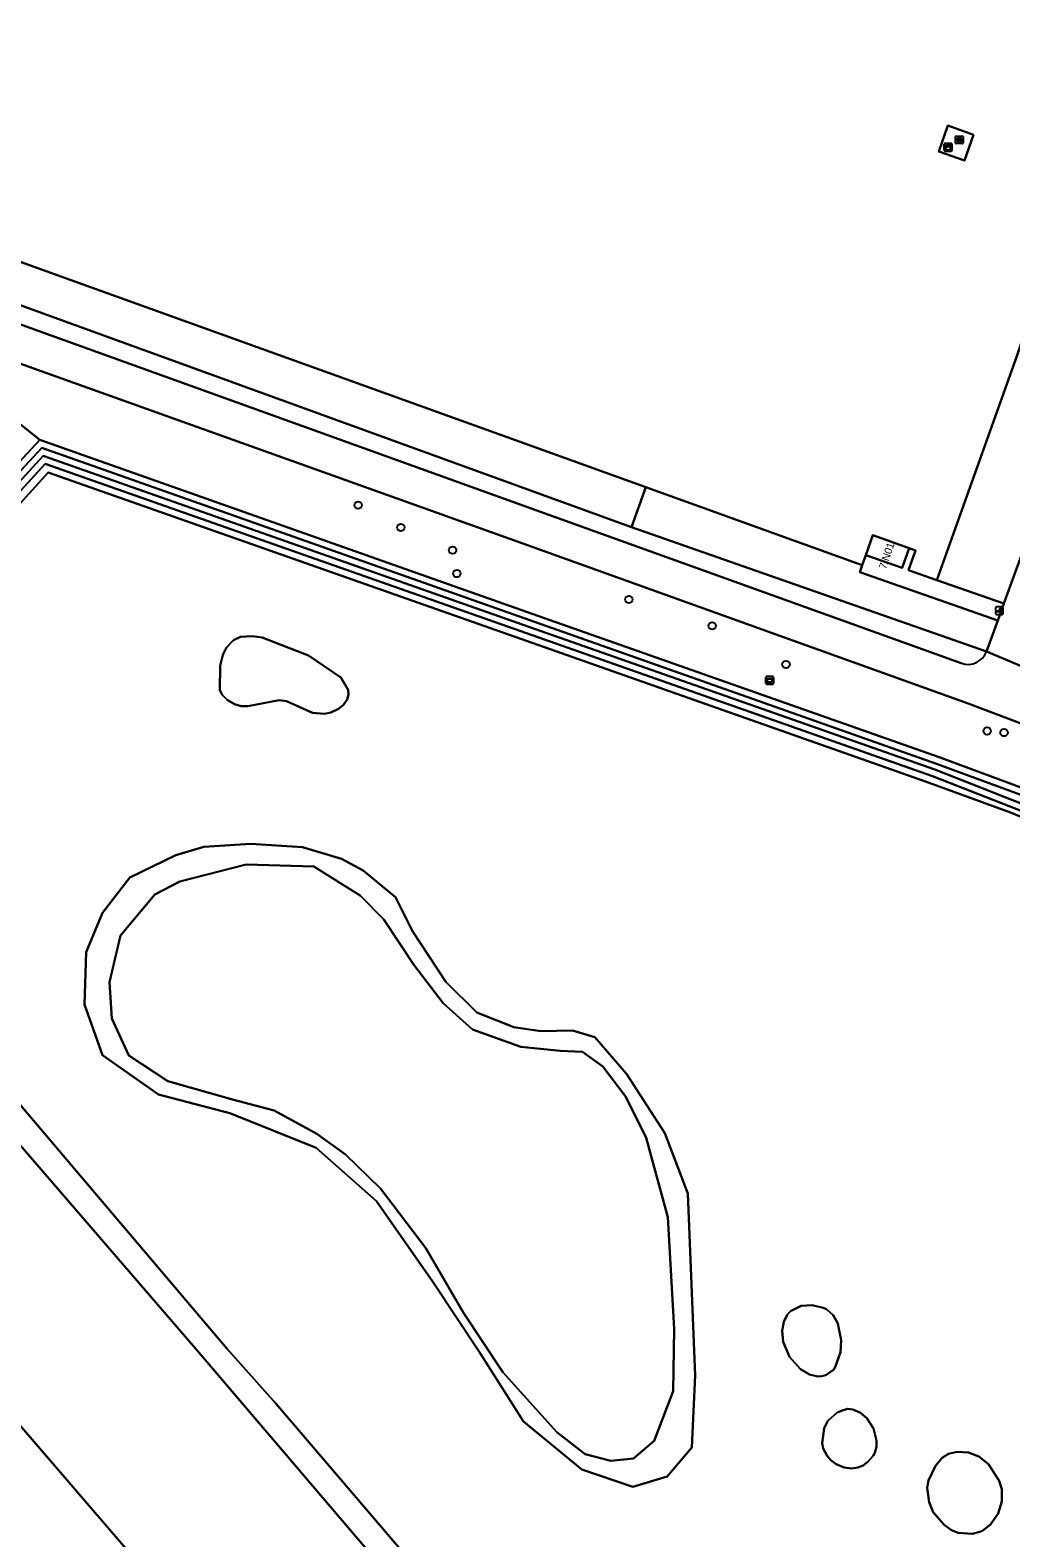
# Model space of a CAD drawing. Extents: x 156061 to 157804, y 383437 to 385640.
# Drawn here: x 156433.8 to 156563.1, y 384975 to 385173.9 of the extents above; entities that cross this region are included whole.
import ezdxf

# ---------------------------------------------------------------- set-up
doc = ezdxf.new("R2010")
doc.units = 0
for name, color, linetype in [('IMGEO_Boom', 7, 'Continuous'), ('IMGEO_Gemengd_bos', 7, 'Continuous'), ('IMGEO_Grasland_overig', 7, 'Continuous'), ('IMGEO_Groenvoorziening', 7, 'Continuous'), ('IMGEO_Kast', 7, 'Continuous'), ('IMGEO_Meer_plas_ven_vijver', 7, 'Continuous'), ('IMGEO_Oever', 7, 'Continuous'), ('IMGEO_Pand', 7, 'Continuous'), ('IMGEO_Pand_nummerreeks', 7, 'Continuous'), ('IMGEO_Poller', 7, 'Continuous'), ('IMGEO_Rijbaan_lokaal_gesloten', 7, 'Continuous'), ('IMGEO_Rioolput', 7, 'Continuous'), ('IMGEO_Terreindeel_open', 7, 'Continuous'), ('IMGEO_Terreindeel_zand', 7, 'Continuous'), ('IMGEO_Verklikker', 7, 'Continuous'), ('IMGEO_Voetpad_open', 7, 'Continuous'), ('IMGEO_Waterloop', 7, 'Continuous')]:
    doc.layers.add(name, color=color, linetype=linetype)

msp = doc.modelspace()

# ---------------------------------------------------------------- linework, layer by layer
at = {"layer": 'IMGEO_Boom'}
for centre in [(156477.05, 385111.22), (156482.67, 385108.28), (156489.5, 385105.3), (156490.07, 385102.2), (156512.75, 385098.79), (156523.74, 385095.32), (156533.49, 385090.22), (156560.03, 385081.44), (156562.25, 385081.23)]:
    msp.add_circle(centre, 0.489, dxfattribs=at)
at = {"layer": 'IMGEO_Gemengd_bos'}
msp.add_lwpolyline([(156581.52, 384855.31), (156560.26, 384878.65), (156543.24, 384898.13), (156530.19, 384913.87), (156511.01, 384935.92), (156506.4, 384941.43), (156500, 384948.5), (156493.79, 384955.24), (156489.93, 384959.71), (156455.58, 385000), (156410.11, 385052.65), (156398.6, 385066.8), (156398.51, 385066.97), (156398.04, 385067.51), (156385.79, 385057.23), (156383.72, 385054.98), (156381.13, 385052.65), (156379.93, 385052.11), (156396.32, 385031.8), (156570.16, 384829.59)], dxfattribs=at)
at = {"layer": 'IMGEO_Grasland_overig'}
for points in [[(156559.95, 385091.94), (156513.09, 385108.31), (156319.71, 385178.59)], [(156325.8, 385173.38), (156337.29, 385169.36), (156500, 385110.73), (156556.61, 385090.38)], [(156559.92, 384883.67), (156545.49, 384899.91), (156526.79, 384922.34), (156500, 384953.15), (156466.17, 384992.71), (156459.73, 385000), (156431.77, 385032.94), (156397.42, 385071.83), (156398.37, 385067.78), (156398.6, 385066.8), (156410.11, 385052.65), (156455.58, 385000), (156489.93, 384959.71), (156493.79, 384955.24), (156500, 384948.5), (156506.4, 384941.43), (156511.01, 384935.92), (156530.19, 384913.87), (156543.24, 384898.13), (156560.26, 384878.65), (156581.52, 384855.31)], [(156570.16, 384829.59), (156396.32, 385031.8), (156379.93, 385052.11), (156377.42, 385051.32), (156377.51, 385050.41), (156377.73, 385048.43)]]:
    msp.add_lwpolyline(points, dxfattribs=at)
msp.add_arc((156557.5, 385092.83), 2.6, 250.2028, 340.1, dxfattribs=at)
at = {"layer": 'IMGEO_Groenvoorziening'}
for points in [[(156585.87, 385195.59), (156576.52, 385168.23), (156563.92, 385130.88), (156553.4, 385101.35), (156562.24, 385098.26), (156565.2, 385106.42), (156577.76, 385144.83), (156586.71, 385170.27), (156596.08, 385197.94)], [(156327.27, 385181.21), (156500, 385119), (156514.99, 385113.6), (156543.55, 385103.32), (156544.01, 385104.64), (156544.92, 385107.25), (156549.72, 385105.57), (156550.57, 385105.27), (156549.65, 385102.67), (156553.4, 385101.35), (156563.92, 385130.88), (156576.52, 385168.23), (156585.87, 385195.59)], [(156590.93, 385073.63), (156578.06, 385077.45), (156567.97, 385081.12), (156557.53, 385085.07), (156500, 385105.74), (156431.78, 385130.12), (156326.22, 385167.86), (156324.12, 385168.82), (156320.16, 385170.64)], [(156316.34, 385168.65), (156316.47, 385168.61), (156317.11, 385168.38), (156326.93, 385164.88), (156430.96, 385127.58), (156429.85, 385123.97), (156435.06, 385119.83), (156500, 385096.91), (156553.67, 385077.98), (156566.96, 385073.06), (156570.74, 385071.38)], [(156567.98, 385069.56), (156552.81, 385075.49), (156500, 385094.07), (156435.74, 385116.68), (156396.11, 385073.31), (156397.42, 385071.83), (156397.25, 385072.57), (156436.13, 385115.54), (156500, 385093.06), (156551.89, 385074.79), (156563.11, 385070.71), (156568.65, 385068.4)], [(156568.65, 385068.4), (156563.11, 385070.71), (156551.89, 385074.79), (156500, 385093.06), (156436.13, 385115.54), (156397.25, 385072.57), (156397.42, 385071.83), (156431.77, 385032.94), (156459.73, 385000), (156466.17, 384992.71), (156500, 384953.15), (156526.79, 384922.34), (156545.49, 384899.91), (156559.92, 384883.67), (156584.04, 384856.9)]]:
    msp.add_lwpolyline(points, dxfattribs=at)
for points in [[(156327.27, 385181.21), (156321.37, 385183.34), (156321.21, 385182.86), (156319.71, 385178.59), (156513.09, 385108.31), (156514.99, 385113.6), (156500, 385119)], [(156554.83, 385161.29), (156558.24, 385160.09), (156557.05, 385156.68), (156553.63, 385157.88)], [(156335.25, 385156.99), (156328.7, 385159.28), (156327.97, 385159.03), (156327.09, 385158.16), (156326.81, 385156.99), (156327.12, 385155.92), (156330.46, 385149.24), (156374.84, 385098.66), (156408.67, 385114.63), (156421.15, 385114.77), (156391.85, 385078.33), (156393.97, 385075.53), (156435.06, 385119.83), (156429.85, 385123.97), (156428.99, 385122.18), (156415.93, 385125.08), (156410.85, 385122.18), (156353.21, 385141.92), (156340.72, 385146.13), (156334.33, 385151.07), (156333.46, 385153.83)], [(156513.09, 385108.31), (156559.95, 385091.94), (156561.42, 385096), (156543.22, 385102.38), (156543.55, 385103.32), (156514.99, 385113.6)], [(156467.59, 385085.38), (156466.64, 385085.51), (156462.5, 385084.7), (156461.61, 385084.72), (156460.74, 385084.97), (156459.76, 385085.57), (156459.09, 385086.23), (156458.8, 385086.82), (156458.86, 385090.03), (156459.2, 385091.48), (156459.68, 385092.44), (156460.61, 385093.4), (156461.52, 385093.88), (156463.07, 385093.96), (156464.4, 385093.76), (156470.5, 385091.4), (156474.77, 385088.49), (156475.71, 385086.87), (156475.79, 385086.24), (156475.58, 385085.6), (156475.1, 385084.88), (156474.45, 385084.35), (156473.46, 385083.89), (156472.62, 385083.71), (156471.03, 385083.82)], [(156513.3, 384981.73), (156506.53, 384984.02), (156498.85, 384990.34), (156493.05, 384999.49), (156486.91, 385008.76), (156479.45, 385019.42), (156471.52, 385026.47), (156460.11, 385031.03), (156450.69, 385033.47), (156443.31, 385038.67), (156440.92, 385045.34), (156441.18, 385052.27), (156443.31, 385057.47), (156446.91, 385062.13), (156452.97, 385065.06), (156456.67, 385066.14), (156462.87, 385066.57), (156469.69, 385066.1), (156474.84, 385064.56), (156477.72, 385063.05), (156481.96, 385059.51), (156484.21, 385055.04), (156488.59, 385048.33), (156492.69, 385044.29), (156497.57, 385042.36), (156501.12, 385041.85), (156505.33, 385041.94), (156508.27, 385041.06), (156512.45, 385036.2), (156517.48, 385028.41), (156520.55, 385020.43), (156521.52, 384996.43), (156521.07, 384986.91), (156517.79, 384983.1)], [(156539.74, 384997.16), (156538.76, 384996.48), (156538.2, 384996.34), (156537.68, 384996.31), (156536.6, 384996.54), (156535.39, 384997.25), (156533.96, 384998.88), (156533.11, 385000.86), (156532.97, 385002.33), (156533.18, 385003.51), (156533.64, 385004.43), (156534.09, 385004.92), (156535.47, 385005.61), (156536.93, 385005.7), (156538.37, 385005.37), (156538.83, 385005.16), (156539.69, 385004.39), (156540.31, 385003.27), (156540.77, 385001.09), (156540.66, 384999.48), (156539.97, 384997.53)], [(156543.65, 384984.57), (156542.95, 384984.27), (156542.13, 384984.16), (156541.16, 384984.29), (156540.11, 384984.72), (156539.4, 384985.24), (156538.9, 384985.82), (156538.4, 384986.79), (156538.24, 384987.48), (156538.54, 384989.46), (156539.02, 384990.43), (156540.23, 384991.52), (156541.02, 384991.87), (156541.63, 384992.02), (156542.31, 384991.94), (156543.31, 384991.49), (156544.13, 384990.79), (156545.02, 384989.41), (156545.43, 384987.83), (156545.41, 384987), (156545.19, 384986.23), (156544.97, 384985.82), (156544.26, 384985.03)], [(156558.05, 384975.54), (156556.2, 384975.69), (156555.34, 384976.01), (156554.33, 384976.72), (156552.92, 384978.38), (156552.38, 384979.7), (156552.12, 384981.59), (156552.28, 384982.55), (156553.21, 384984.49), (156554.09, 384985.54), (156554.94, 384986.11), (156556.01, 384986.35), (156557.54, 384986.25), (156558.94, 384985.74), (156560.19, 384984.72), (156561.61, 384982.54), (156561.96, 384981.41), (156561.98, 384979.79), (156561.49, 384978.22), (156560.48, 384976.77), (156559.43, 384975.98), (156559.04, 384975.8)]]:
    msp.add_lwpolyline(points, close=True, dxfattribs=at)
at = {"layer": 'IMGEO_Kast'}
for p, q in [((156554.37, 385158), (156554.37, 385158.84)), ((156554.37, 385158.84), (156554.37, 385158)), ((156554.44, 385158.93), (156555.28, 385158.93)), ((156555.28, 385158.93), (156554.44, 385158.93)), ((156555.29, 385157.93), (156554.45, 385157.93)), ((156554.45, 385157.93), (156555.29, 385157.93)), ((156555.37, 385158.85), (156555.37, 385158.01)), ((156555.37, 385158.01), (156555.37, 385158.85))]:
    msp.add_line(p, q, dxfattribs=at)
for points in [[(156554.56, 385158.72), (156555.16, 385158.72), (156555.16, 385158.63), (156554.56, 385158.63), (156554.56, 385158.72)], [(156554.56, 385158.54), (156555.16, 385158.54), (156555.16, 385158.05), (156554.56, 385158.05), (156554.56, 385158.54)]]:
    msp.add_lwpolyline(points, dxfattribs=at)
msp.add_circle((156554.65, 385158.39), 0.0377, dxfattribs=at)
for centre, start, end in [((156554.45, 385158.85), 92.4484, 184.2845), ((156554.45, 385158.85), 92.4484, 184.2845), ((156554.45, 385158.01), 182.4484, 274.2845), ((156554.45, 385158.01), 182.4484, 274.2845), ((156555.29, 385158.85), 2.4484, 94.2845), ((156555.29, 385158.85), 2.4484, 94.2845), ((156555.29, 385158.01), 272.4484, 4.2845), ((156555.29, 385158.01), 272.4484, 4.2845)]:
    msp.add_arc(centre, 0.0779, start, end, dxfattribs=at)
at = {"layer": 'IMGEO_Meer_plas_ven_vijver'}
msp.add_lwpolyline([(156445.68, 385054.45), (156444.22, 385048.3), (156444.55, 385043.52), (156446.78, 385038.64), (156451.95, 385035.27), (156460.48, 385032.84), (156465.95, 385031.36), (156471.58, 385028.29), (156475.37, 385025.56), (156479.99, 385021.1), (156485.96, 385013.24), (156490.93, 385004.71), (156496.12, 384996.86), (156503.27, 384988.96), (156506.97, 384986.06), (156510.39, 384985.15), (156513.38, 384985.49), (156516.11, 384987.8), (156518.59, 384994.35), (156518.73, 385002.56), (156517.9, 385017.3), (156515.05, 385027.76), (156512.35, 385033.19), (156509.32, 385037.19), (156506.63, 385039.12), (156503.69, 385039.25), (156498.5, 385039.79), (156492.12, 385042.07), (156488.26, 385045.55), (156484.39, 385050.6), (156480.43, 385056.57), (156477.31, 385059.75), (156471.19, 385063.57), (156462.27, 385063.85), (156453.5, 385061.59), (156450.21, 385059.87)], close=True, dxfattribs=at)
at = {"layer": 'IMGEO_Oever'}
for points in [[(156435.06, 385119.83), (156393.97, 385075.53), (156396.11, 385073.31), (156435.74, 385116.68), (156500, 385094.07), (156552.81, 385075.49), (156567.98, 385069.56)], [(156568.31, 385070.4), (156553.13, 385076.34), (156500.3, 385094.93), (156435.47, 385117.74), (156396.1, 385074.63), (156395.22, 385075.54), (156435.32, 385118.78), (156499.7, 385096.06), (156553.36, 385077.12), (156566.62, 385072.22)], [(156570.74, 385071.38), (156566.96, 385073.06), (156553.67, 385077.98), (156500, 385096.91), (156435.06, 385119.83)]]:
    msp.add_lwpolyline(points, dxfattribs=at)
for points in [[(156484.21, 385055.04), (156481.96, 385059.51), (156477.72, 385063.05), (156474.84, 385064.56), (156469.69, 385066.1), (156462.87, 385066.57), (156456.67, 385066.14), (156452.97, 385065.06), (156446.91, 385062.13), (156443.31, 385057.47), (156441.18, 385052.27), (156440.92, 385045.34), (156443.31, 385038.67), (156450.69, 385033.47), (156460.11, 385031.03), (156471.52, 385026.47), (156479.45, 385019.42), (156486.91, 385008.76), (156493.05, 384999.49), (156498.85, 384990.34), (156506.53, 384984.02), (156513.3, 384981.73), (156517.79, 384983.1), (156521.07, 384986.91), (156521.52, 384996.43), (156520.55, 385020.43), (156517.48, 385028.41), (156512.45, 385036.2), (156508.27, 385041.06), (156505.33, 385041.94), (156501.12, 385041.85), (156497.57, 385042.36), (156492.69, 385044.29), (156488.59, 385048.33)], [(156445.68, 385054.45), (156450.21, 385059.87), (156453.5, 385061.59), (156462.27, 385063.85), (156471.19, 385063.57), (156477.31, 385059.75), (156480.43, 385056.57), (156484.39, 385050.6), (156488.26, 385045.55), (156492.12, 385042.07), (156498.5, 385039.79), (156503.69, 385039.25), (156506.63, 385039.12), (156509.32, 385037.19), (156512.35, 385033.19), (156515.05, 385027.76), (156517.9, 385017.3), (156518.73, 385002.56), (156518.59, 384994.35), (156516.11, 384987.8), (156513.38, 384985.49), (156510.39, 384985.15), (156506.97, 384986.06), (156503.27, 384988.96), (156496.12, 384996.86), (156490.93, 385004.71), (156485.96, 385013.24), (156479.99, 385021.1), (156475.37, 385025.56), (156471.58, 385028.29), (156465.95, 385031.36), (156460.48, 385032.84), (156451.95, 385035.27), (156446.78, 385038.64), (156444.55, 385043.52), (156444.22, 385048.3)]]:
    msp.add_lwpolyline(points, close=True, dxfattribs=at)
at = {"layer": 'IMGEO_Pand'}
msp.add_lwpolyline([(156549.72, 385105.57), (156544.92, 385107.25), (156544.01, 385104.64), (156548.8, 385102.96)], close=True, dxfattribs=at)
at = {"layer": 'IMGEO_Poller'}
for p, q in [((156561.14, 385097.71), (156561.14, 385096.9)), ((156561.14, 385097.71), (156561.14, 385096.9)), ((156562.04, 385097.81), (156561.23, 385097.81)), ((156562.04, 385097.81), (156561.23, 385097.81)), ((156561.23, 385096.81), (156562.04, 385096.81)), ((156561.23, 385096.81), (156562.04, 385096.81)), ((156562.13, 385096.9), (156562.13, 385097.71)), ((156562.13, 385096.9), (156562.13, 385097.71))]:
    msp.add_line(p, q, dxfattribs=at)
for points in [[(156561.77, 385097.16), (156561.26, 385097.16), (156561.69, 385097.44)], [(156561.82, 385097.54), (156561.8, 385097.46), (156561.68, 385097.67)], [(156561.68, 385097.67), (156561.91, 385097.6), (156561.84, 385097.57)], [(156561.83, 385096.99), (156561.9, 385097.22), (156561.93, 385097.15)], [(156561.97, 385097.13), (156562.04, 385097.12), (156561.83, 385096.99)]]:
    msp.add_lwpolyline(points, dxfattribs=at)
for centre, radius, start, end in [((156561.23, 385097.71), 0.0946, 90, 180), ((156561.23, 385097.71), 0.0946, 90, 180), ((156561.23, 385096.9), 0.0946, 180, 270), ((156561.23, 385096.9), 0.0946, 180, 270), ((156561.44, 385097.21), 0.332, 351.3247, 42.4854), ((156561.46, 385097.22), 0.476, 351.7527, 41.1691), ((156561.46, 385097.22), 0.516, 349.3569, 42.2912), ((156562.04, 385097.71), 0.0946, 0, 90), ((156562.04, 385097.71), 0.0946, 0, 90), ((156562.04, 385096.9), 0.0946, 270, 0), ((156562.04, 385096.9), 0.0946, 270, 0)]:
    msp.add_arc(centre, radius, start, end, dxfattribs=at)
at = {"layer": 'IMGEO_Rijbaan_lokaal_gesloten'}
for points in [[(156602.54, 385217.74), (156601.08, 385213.63), (156596.08, 385197.94), (156586.71, 385170.27), (156577.76, 385144.83), (156565.2, 385106.42), (156562.24, 385098.26), (156561.42, 385096), (156559.95, 385091.94), (156566.3, 385089.23)], [(156337.29, 385169.36), (156325.8, 385173.38), (156324.12, 385168.82), (156326.22, 385167.86), (156431.78, 385130.12), (156500, 385105.74), (156557.53, 385085.07), (156567.97, 385081.12), (156578.06, 385077.45), (156590.93, 385073.63), (156601.32, 385070.53), (156604.14, 385073.81), (156569.75, 385086.11)], [(156556.61, 385090.38), (156500, 385110.73), (156337.29, 385169.36)], [(156566.3, 385089.23), (156559.95, 385091.94)]]:
    msp.add_lwpolyline(points, dxfattribs=at)
msp.add_arc((156557.5, 385092.83), 2.6, 250.2028, 340.1, dxfattribs=at)
at = {"layer": 'IMGEO_Rioolput'}
for p, q in [((156555.85, 385159), (156555.85, 385159.85)), ((156555.93, 385159.92), (156556.78, 385159.92)), ((156556.34, 385159.7), (156556.37, 385159.7)), ((156556.85, 385159.85), (156556.85, 385159)), ((156556.78, 385158.92), (156555.93, 385158.92)), ((156556.11, 385159.42), (156556.11, 385159.43)), ((156556.15, 385159.47), (156556.55, 385159.47)), ((156556.55, 385159.38), (156556.15, 385159.38)), ((156556.36, 385159.14), (156556.34, 385159.14)), ((156556.6, 385159.43), (156556.6, 385159.42))]:
    msp.add_line(p, q, dxfattribs=at)
for points in [[(156555.85, 385159), (156555.85, 385159.85)], [(156555.93, 385159.92), (156556.78, 385159.92)], [(156556.85, 385159.85), (156556.85, 385159)], [(156556.78, 385158.92), (156555.93, 385158.92)]]:
    msp.add_lwpolyline(points, dxfattribs=at)
for centre, radius, start, end in [((156555.93, 385159.85), 0.0765, 91.552, 178.448), ((156555.93, 385159.85), 0.0765, 91.552, 178.448), ((156556.78, 385159.85), 0.0765, 1.552, 88.448), ((156556.78, 385159.85), 0.0765, 1.552, 88.448), ((156555.93, 385159), 0.0765, 181.552, 268.448), ((156555.93, 385159), 0.0765, 181.552, 268.448), ((156556.15, 385159.43), 0.0403, 85.8775, 175.7526), ((156556.15, 385159.42), 0.0366, 178.938, 274.7102), ((156556.56, 385159.43), 0.0386, 1.7309, 96.639), ((156556.55, 385159.42), 0.043, 264.8664, 352.4533), ((156556.78, 385159), 0.0765, 271.552, 358.448), ((156556.78, 385159), 0.0765, 271.552, 358.448)]:
    msp.add_arc(centre, radius, start, end, dxfattribs=at)
for centre, major_axis, ratio, start_param, end_param in [((156556.34, 385159.42), (-0.387, 0.002), 0.722429, 4.712389, 7.853982), ((156556.36, 385159.42), (-0.39, 0.002), 0.717154, 1.570796, 4.712389)]:
    msp.add_ellipse(centre, major_axis=major_axis, ratio=ratio, start_param=start_param, end_param=end_param, dxfattribs=at)
at = {"layer": 'IMGEO_Terreindeel_open'}
msp.add_lwpolyline([(156557.05, 385156.68), (156558.24, 385160.09), (156554.83, 385161.29), (156553.63, 385157.88)], close=True, dxfattribs=at)
at = {"layer": 'IMGEO_Terreindeel_zand'}
for points in [[(156460.61, 385093.4), (156459.68, 385092.44), (156459.2, 385091.48), (156458.86, 385090.03), (156458.8, 385086.82), (156459.09, 385086.23), (156459.76, 385085.57), (156460.74, 385084.97), (156461.61, 385084.72), (156462.5, 385084.7), (156466.64, 385085.51), (156467.59, 385085.38), (156471.03, 385083.82), (156472.62, 385083.71), (156473.46, 385083.89), (156474.45, 385084.35), (156475.1, 385084.88), (156475.58, 385085.6), (156475.79, 385086.24), (156475.71, 385086.87), (156474.77, 385088.49), (156470.5, 385091.4), (156464.4, 385093.76), (156463.07, 385093.96), (156461.52, 385093.88)], [(156535.47, 385005.61), (156534.09, 385004.92), (156533.64, 385004.43), (156533.18, 385003.51), (156532.97, 385002.33), (156533.11, 385000.86), (156533.96, 384998.88), (156535.39, 384997.25), (156536.6, 384996.54), (156537.68, 384996.31), (156538.2, 384996.34), (156538.76, 384996.48), (156539.74, 384997.16), (156539.97, 384997.53), (156540.66, 384999.48), (156540.77, 385001.09), (156540.31, 385003.27), (156539.69, 385004.39), (156538.83, 385005.16), (156538.37, 385005.37), (156536.93, 385005.7)], [(156540.23, 384991.52), (156539.02, 384990.43), (156538.54, 384989.46), (156538.24, 384987.48), (156538.4, 384986.79), (156538.9, 384985.82), (156539.4, 384985.24), (156540.11, 384984.72), (156541.16, 384984.29), (156542.13, 384984.16), (156542.95, 384984.27), (156543.65, 384984.57), (156544.26, 384985.03), (156544.97, 384985.82), (156545.19, 384986.23), (156545.41, 384987), (156545.43, 384987.83), (156545.02, 384989.41), (156544.13, 384990.79), (156543.31, 384991.49), (156542.31, 384991.94), (156541.63, 384992.02), (156541.02, 384991.87)], [(156553.21, 384984.49), (156552.28, 384982.55), (156552.12, 384981.59), (156552.38, 384979.7), (156552.92, 384978.38), (156554.33, 384976.72), (156555.34, 384976.01), (156556.2, 384975.69), (156558.05, 384975.54), (156559.04, 384975.8), (156559.43, 384975.98), (156560.48, 384976.77), (156561.49, 384978.22), (156561.98, 384979.79), (156561.96, 384981.41), (156561.61, 384982.54), (156560.19, 384984.72), (156558.94, 384985.74), (156557.54, 384986.25), (156556.01, 384986.35), (156554.94, 384986.11), (156554.09, 384985.54)]]:
    msp.add_lwpolyline(points, close=True, dxfattribs=at)
at = {"layer": 'IMGEO_Verklikker'}
for p, q in [((156530.83, 385087.71), (156530.83, 385088.51)), ((156530.83, 385088.51), (156530.83, 385087.71)), ((156530.93, 385088.61), (156531.72, 385088.61)), ((156531.72, 385088.61), (156530.93, 385088.61)), ((156531.82, 385088.51), (156531.82, 385087.71)), ((156531.82, 385087.71), (156531.82, 385088.51)), ((156531.72, 385087.61), (156530.93, 385087.61)), ((156530.93, 385087.61), (156531.72, 385087.61))]:
    msp.add_line(p, q, dxfattribs=at)
for points in [[(156530.93, 385088.34), (156531.72, 385088.34), (156531.72, 385087.88), (156530.93, 385087.88), (156530.93, 385088.34)], [(156531, 385088.28), (156531, 385087.94), (156531.66, 385087.94), (156531.66, 385088.28), (156531, 385088.28)]]:
    msp.add_lwpolyline(points, dxfattribs=at)
for centre, start, end in [((156530.93, 385088.51), 90, 180), ((156530.93, 385088.51), 90, 180), ((156531.72, 385088.51), 0, 90), ((156531.72, 385088.51), 360, 90), ((156530.93, 385087.71), 180, 270), ((156530.93, 385087.71), 180, 270), ((156531.72, 385087.71), 270, 0), ((156531.72, 385087.71), 270, 0)]:
    msp.add_arc(centre, 0.1, start, end, dxfattribs=at)
at = {"layer": 'IMGEO_Voetpad_open'}
msp.add_lwpolyline([(156544.01, 385104.64), (156543.55, 385103.32), (156543.22, 385102.38), (156561.42, 385096), (156562.24, 385098.26), (156553.4, 385101.35), (156549.65, 385102.67), (156550.57, 385105.27), (156549.72, 385105.57), (156548.8, 385102.96)], close=True, dxfattribs=at)
at = {"layer": 'IMGEO_Waterloop'}
msp.add_lwpolyline([(156566.62, 385072.22), (156553.36, 385077.12), (156499.7, 385096.06), (156435.32, 385118.78), (156395.22, 385075.54), (156396.1, 385074.63), (156435.47, 385117.74), (156500.3, 385094.93), (156553.13, 385076.34), (156568.31, 385070.4)], dxfattribs=at)

# ---------------------------------------------------------------- texts
at = {"layer": 'IMGEO_Pand_nummerreeks'}
msp.add_text('7/N01', height=1, rotation=71.2171, dxfattribs=at).set_placement((156546.66, 385102.72))

doc.saveas('drawing.dxf')
